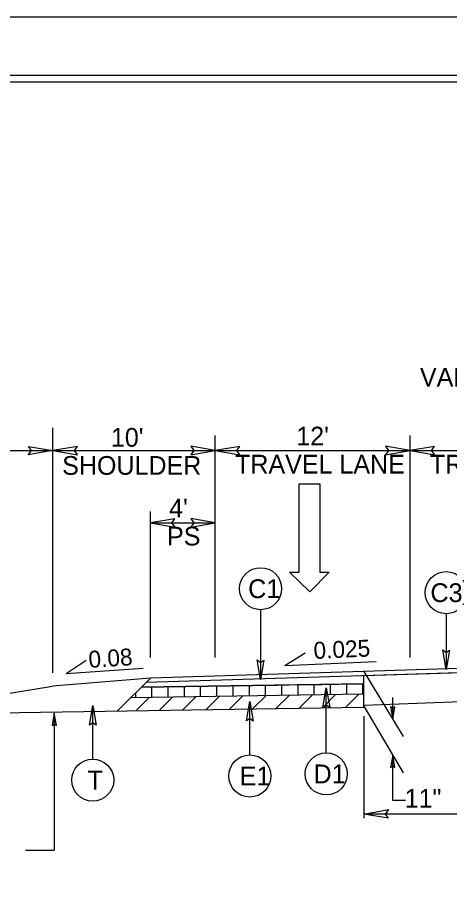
# Model space of a CAD drawing. Extents: x 2176156 to 2177167, y 76401 to 76644.
# Drawn here: x 2176758.9 to 2176785.6, y 76577.2 to 76630.5 of the extents above; entities that cross this region are included whole.
import ezdxf

# ---------------------------------------------------------------- set-up
doc = ezdxf.new("R2010")
doc.units = 0
for name, color, linetype in [('Exist Building', 7, 'Continuous'), ('Exist Roads Curbs', 7, 'Continuous'), ('Exist Roads EOP Other', 7, 'Continuous'), ('Exist Roads Soil', 7, 'Continuous'), ('Exist Structure Minor Culvert Topo', 7, 'Continuous'), ('Exist Structure Minor Drop Inlet', 7, 'Continuous'), ('Exist Utilities Other Pole CELL', 7, 'Continuous'), ('Model Boundary Lines Text', 7, 'Continuous'), ('Old_Level_1', 7, 'Continuous'), ('Old_Level_3', 7, 'Continuous'), ('Prop North Arrow NAD83 for Plan Sheets CELL', 7, 'Continuous'), ('Sheet Cutting Line CELL', 7, 'Continuous'), ('Sheet Data Field CELL', 7, 'Continuous'), ('Sheet Plan CELL', 7, 'Continuous'), ('Sheet Plot Border Outside CELL', 7, 'Continuous'), ('Sheet Sticker Exception Certification CELL', 7, 'Continuous')]:
    doc.layers.add(name, color=color, linetype=linetype)

msp = doc.modelspace()

# ---------------------------------------------------------------- linework, layer by layer
at = {"layer": 'Exist Building'}
for p, q in [((2176780.289, 76587.96), (2176780.289, 76589.911)), ((2176750.611, 76587.518), (2176780.289, 76587.96))]:
    msp.add_line(p, q, dxfattribs=at)
at = {"layer": 'Exist Roads Curbs'}
for p, q in [((2176797.146, 76590.687), (2176767.146, 76589.751)), ((2176796.478, 76590.416), (2176766.886, 76589.493))]:
    msp.add_line(p, q, dxfattribs=at)
at = {"layer": 'Exist Roads EOP Other'}
for p, q in [((2176796.426, 76590.664), (2176767.146, 76589.751)), ((2176767.146, 76589.751), (2176761.111, 76589.268)), ((2176767.146, 76589.751), (2176766.886, 76589.493))]:
    msp.add_line(p, q, dxfattribs=at)
for points in [[(2176773.445, 76589.312), (2176774.959, 76589.334), (2176776.433, 76589.356), (2176777.013, 76589.365), (2176777.705, 76589.375), (2176778.76, 76589.391), (2176780.289, 76589.414), (2176780.289, 76589.911), (2176796.478, 76590.416)], [(2176766.886, 76589.493), (2176766.602, 76589.21), (2176773.445, 76589.312)]]:
    msp.add_lwpolyline(points, dxfattribs=at)
at = {"layer": 'Exist Roads Soil'}
for p, q in [((2176767.146, 76589.751), (2176765.117, 76587.734)), ((2176733.159, 76584.61), (2176761.111, 76589.268)), ((2176780.289, 76589.414), (2176766.602, 76589.21)), ((2176780.289, 76588.766), (2176765.941, 76588.553))]:
    msp.add_line(p, q, dxfattribs=at)
at = {"layer": 'Exist Structure Minor Drop Inlet'}
for p, q in [((2176776.305, 76596.288), (2176776.305, 76601.72)), ((2176776.305, 76601.72), (2176777.585, 76601.72)), ((2176777.585, 76601.72), (2176777.585, 76596.288)), ((2176776.964, 76595.066), (2176775.723, 76596.288)), ((2176775.723, 76596.288), (2176776.305, 76596.288)), ((2176778.167, 76596.288), (2176776.964, 76595.066)), ((2176777.585, 76596.288), (2176778.167, 76596.288))]:
    msp.add_line(p, q, dxfattribs=at)
at = {"layer": 'Exist Utilities Other Pole CELL'}
for p, q in [((2176775.434, 76590.528), (2176776.674, 76591.323)), ((2176761.959, 76590.053), (2176763.184, 76590.872)), ((2176775.434, 76590.528), (2176781.061, 76590.79)), ((2176761.959, 76590.053), (2176766.706, 76590.367))]:
    msp.add_line(p, q, dxfattribs=at)
at = {"layer": 'Model Boundary Lines Text'}
for p, q in [((2176767.242, 76588.572), (2176767.242, 76589.22)), ((2176768.242, 76588.587), (2176768.242, 76589.234)), ((2176769.242, 76588.602), (2176769.242, 76589.249)), ((2176770.242, 76588.617), (2176770.242, 76589.264)), ((2176771.242, 76588.632), (2176771.242, 76589.279)), ((2176772.242, 76588.646), (2176772.242, 76589.294)), ((2176773.242, 76588.661), (2176773.242, 76589.309)), ((2176774.242, 76588.676), (2176774.242, 76589.324)), ((2176775.242, 76588.691), (2176775.242, 76589.339)), ((2176776.242, 76588.706), (2176776.242, 76589.354)), ((2176777.242, 76588.721), (2176777.242, 76589.368)), ((2176778.242, 76588.736), (2176778.242, 76589.383)), ((2176779.242, 76588.751), (2176779.242, 76589.398)), ((2176780.242, 76588.765), (2176780.242, 76589.413)), ((2176766.242, 76588.557), (2176766.242, 76588.852)), ((2176766.253, 76587.751), (2176767.072, 76588.569)), ((2176767.689, 76587.772), (2176768.507, 76588.591)), ((2176769.124, 76587.794), (2176769.943, 76588.612)), ((2176770.56, 76587.815), (2176771.378, 76588.634)), ((2176771.995, 76587.836), (2176772.814, 76588.655)), ((2176773.431, 76587.858), (2176774.25, 76588.676)), ((2176774.867, 76587.879), (2176775.685, 76588.698)), ((2176776.302, 76587.9), (2176777.121, 76588.719)), ((2176777.738, 76587.922), (2176778.556, 76588.74)), ((2176779.173, 76587.943), (2176779.992, 76588.762))]:
    msp.add_line(p, q, dxfattribs=at)
at = {"layer": 'Old_Level_1'}
for points in [[(2176759.636, 76604.04), (2176761.146, 76603.78), (2176759.628, 76603.511), (2176759.821, 76603.78)], [(2176762.655, 76604.04), (2176761.146, 76603.78), (2176762.664, 76603.511), (2176762.471, 76603.78)], [(2176769.636, 76603.52), (2176771.146, 76603.78), (2176769.628, 76604.048), (2176769.821, 76603.78)], [(2176772.655, 76604.04), (2176771.146, 76603.78), (2176772.664, 76603.511), (2176772.471, 76603.78)], [(2176781.636, 76603.52), (2176783.146, 76603.78), (2176781.628, 76604.048), (2176781.821, 76603.78)], [(2176784.655, 76604.04), (2176783.146, 76603.78), (2176784.664, 76603.511), (2176784.471, 76603.78)], [(2176768.655, 76599.579), (2176767.146, 76599.319), (2176768.664, 76599.051), (2176768.471, 76599.319)], [(2176769.636, 76599.059), (2176771.146, 76599.319), (2176769.628, 76599.588), (2176769.821, 76599.319)], [(2176781.945, 76587.983), (2176782.077, 76587.228), (2176782.209, 76587.988), (2176782.075, 76587.891)], [(2176761.356, 76586.835), (2176761.226, 76587.59), (2176761.092, 76586.831), (2176761.226, 76586.927)], [(2176782.209, 76584.249), (2176782.077, 76585.004), (2176781.945, 76584.244), (2176782.079, 76584.341)], [(2176781.798, 76581.127), (2176780.289, 76581.387), (2176781.807, 76581.656), (2176781.614, 76581.387)]]:
    msp.add_lwpolyline(points, close=True, dxfattribs=at)
at = {"layer": 'Old_Level_3'}
for p, q in [((2176761.146, 76590.089), (2176761.146, 76605.175)), ((2176771.146, 76591.02), (2176771.146, 76604.707)), ((2176783.146, 76591.02), (2176783.146, 76604.707)), ((2176733.146, 76603.78), (2176797.146, 76603.78)), ((2176767.146, 76591.02), (2176767.146, 76600.029)), ((2176767.146, 76599.319), (2176771.146, 76599.319)), ((2176780.289, 76590.161), (2176782.714, 76586.153)), ((2176782.077, 76587.228), (2176782.077, 76588.557)), ((2176780.289, 76588.023), (2176782.714, 76583.929)), ((2176761.226, 76587.59), (2176761.226, 76579.165)), ((2176780.289, 76587.415), (2176780.289, 76581.134)), ((2176782.077, 76582.228), (2176782.077, 76585.004)), ((2176782.857, 76582.228), (2176782.077, 76582.228)), ((2176804.068, 76581.387), (2176780.289, 76581.387)), ((2176759.459, 76579.165), (2176761.226, 76579.165))]:
    msp.add_line(p, q, dxfattribs=at)
at = {"layer": 'Prop North Arrow NAD83 for Plan Sheets CELL'}
for p, q in [((2176773.936, 76593.972), (2176773.936, 76589.669)), ((2176785.367, 76593.727), (2176785.367, 76590.287)), ((2176777.98, 76585.154), (2176777.98, 76589.154)), ((2176763.597, 76584.771), (2176763.597, 76588.067)), ((2176773.273, 76585.025), (2176773.273, 76588.321))]:
    msp.add_line(p, q, dxfattribs=at)
for points in [[(2176785.574, 76591.487), (2176785.367, 76590.287), (2176785.154, 76591.493), (2176785.367, 76591.34)], [(2176774.142, 76590.869), (2176773.936, 76589.669), (2176773.722, 76590.876), (2176773.936, 76590.722)], [(2176777.773, 76587.954), (2176777.98, 76589.154), (2176778.193, 76587.948), (2176777.98, 76588.101)], [(2176763.39, 76586.867), (2176763.597, 76588.067), (2176763.81, 76586.86), (2176763.597, 76587.013)], [(2176773.066, 76587.121), (2176773.273, 76588.321), (2176773.486, 76587.114), (2176773.273, 76587.267)]]:
    msp.add_lwpolyline(points, close=True, dxfattribs=at)
for centre in [(2176773.936, 76595.268), (2176785.367, 76595.023), (2176763.597, 76583.475), (2176773.273, 76583.729), (2176777.98, 76583.858)]:
    msp.add_circle(centre, 1.296, dxfattribs=at)
at = {"layer": 'Sheet Cutting Line CELL'}
msp.add_lwpolyline([(2176898.707, 76630.475), (2176629.267, 76630.475), (2176629.267, 76454.475), (2176898.707, 76454.475)], close=True, dxfattribs=at)
at = {"layer": 'Sheet Data Field CELL'}
msp.add_lwpolyline([(2176895.987, 76626.475), (2176655.987, 76626.475), (2176655.987, 76458.475), (2176895.987, 76458.475)], close=True, dxfattribs=at)
at = {"layer": 'Sheet Plan CELL'}
msp.add_line((2176780.289, 76588.096), (2176797.146, 76588.706), dxfattribs=at)
at = {"layer": 'Sheet Plot Border Outside CELL'}
msp.add_lwpolyline([(2176897.987, 76626.883), (2176631.347, 76626.883), (2176631.347, 76458.067), (2176897.987, 76458.067)], close=True, dxfattribs=at)
at = {"layer": 'Sheet Sticker Exception Certification CELL'}
msp.add_line((2176898.707, 76630.475), (2176629.267, 76630.475), dxfattribs=at)

# ---------------------------------------------------------------- texts
at = {"layer": 'Exist Structure Minor Culvert Topo'}
for s, height, p in [("VARIES 0'-5'", 1.15334, (2176783.751, 76607.722)), ("10' ", 1.1533, (2176764.715, 76604.017)), ("12'", 1.1533, (2176776.132, 76604.095)), ('SHOULDER', 1.1533, (2176761.714, 76602.287)), ('TRAVEL LANE', 1.15334, (2176772.363, 76602.365)), ('TRAVEL LANE', 1.15334, (2176784.363, 76602.365)), ("4' ", 1.1533, (2176768.302, 76599.661)), ('PS', 1.1533, (2176768.172, 76597.931))]:
    msp.add_text(s, height=height, dxfattribs=at).set_placement(p)
at = {"layer": 'Exist Utilities Other Pole CELL'}
for s, rotation, p in [('0.025', 2.6676, (2176777.22, 76590.933)), ('0.08', 3.7801, (2176763.369, 76590.383))]:
    msp.add_text(s, height=1.0429, rotation=rotation, dxfattribs=at).set_placement(p)
at = {"layer": 'Prop North Arrow NAD83 for Plan Sheets CELL'}
for s, p in [('C1', (2176773.167, 76594.688)), ('C3', (2176784.394, 76594.443)), ('E1', (2176772.644, 76583.149)), ('D1', (2176777.195, 76583.278)), ('T', (2176763.27, 76582.895))]:
    msp.add_text(s, height=1.16, rotation=0.0003, dxfattribs=at).set_placement(p)
msp.add_text('11"', height=1.1533, dxfattribs=at).set_placement((2176782.809, 76581.778))

doc.saveas('drawing.dxf')
